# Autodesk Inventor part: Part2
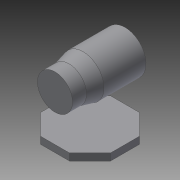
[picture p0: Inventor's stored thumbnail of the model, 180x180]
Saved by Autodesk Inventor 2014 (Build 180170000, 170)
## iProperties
Created: 2021-01
Part Number: Part2
Material: Generic
Document SubType Name: Modeling
Designer: kh
Density: 1 g/cm^3
Appearance: Default
Author: kh
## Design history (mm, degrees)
sketch "Sketch1" dims "d0" = 100
  geometry: L1 (20.711, 50)-(50, 20.711); L2 (50, 20.711)-(50, -20.711); L3 (50, -20.711)-(20.711, -50); L4 (20.711, -50)-(-20.711, -50); L5 (-20.711, -50)-(-50, -20.711); L6 (-50, -20.711)-(-50, 20.711); L7 (-50, 20.711)-(-20.711, 50); L8 (-20.711, 50)-(20.711, 50); L9 (0, 0)-(0, 50); 4 further points
  constraints: 18 end point, 3 coincident, 1 midpoint, 1 vertical, 20 other
  dimensions: "d12" = 50 distance of L9.start L9.end
extrude "Extrusion1" new body sketch "Sketch1" distance "d1" = 10; taper "d2" = 0 deg
workplane "Work Plane1"
sketch "Sketch2"
  geometry: L1 (-19.134, 0)-(19.134, 0) reference; L2 (-19.134, 0)-(-19.134, 10) reference; L3 (19.134, 10)-(-19.134, 10) reference; L4 (19.134, 0)-(19.134, 10) reference; L5 (-46.194, 0)-(-19.134, 0) reference; L6 (-46.194, 0)-(-46.194, 10) reference; L7 (-19.134, 10)-(-46.194, 10) reference; L8 (-19.134, 0)-(-19.134, 10) reference; L9 (19.134, 0)-(46.194, 0) reference; L10 (19.134, 0)-(19.134, 10) reference; L11 (46.194, 10)-(19.134, 10) reference; L12 (46.194, 0)-(46.194, 10) reference; L13 (-50, 75)-(-30, 75); L14 (-30, 75)-(-30, 100); L15 (-30, 100)-(-50, 100); L16 (-50, 100)-(-50, 75); L17 (-30, 75)-(-10, 75); L18 (-10, 75)-(-10, 105); L19 (-30, 100)-(-30, 75); L20 (-10, 75)-(50, 75); L21 (50, 75)-(50, 105); L22 (50, 105)-(-10, 105); L23 (-10, 105)-(-10, 75); L24 (-30, 100)-(-10, 105); L25 (-50, 0)-(-20.711, 0) reference; L26 (-50, 0)-(-50, 10) reference; L27 (-20.711, 10)-(-50, 10) reference; L28 (-20.711, 0)-(-20.711, 10) reference; L29 (-20.711, 0)-(20.711, 0) reference; L30 (-20.711, 0)-(-20.711, 10) reference; L31 (20.711, 10)-(-20.711, 10) reference; L32 (20.711, 0)-(20.711, 10) reference; L33 (20.711, 0)-(50, 0) reference; L34 (20.711, 0)-(20.711, 10) reference; L35 (50, 10)-(20.711, 10) reference; L36 (50, 0)-(50, 10) reference
  constraints: 24 end point, 5 parallel, 3 horizontal, 3 perpendicular, 1 collinear
  dimensions: "d5" = 50 diameter of L15 L13; "d7" = 60 diameter of L22 L20; "d8" = 100 distance between parallel lines of L21 L16; "d9" = 40 distance between parallel lines of L16 L18; "d10" = 20 distance between parallel lines of L16 L14; "d14" = 75 distance of L13.start L25.start
revolve "Revolution2" sketch "Sketch2" stored, may be unused: angle "d15" = 90 deg
workplane "Work Plane2"
sketch "Sketch3"
  geometry: L1 (-50, 50)-(-50, 100) reference; L2 (50, 45)-(50, 105) reference; L3 (-50, 75)-(50, 75); L4 (50, 75)-(35, 75); L5 (35, 75)-(35, 96); L6 (35, 96)-(50, 96); L7 (50, 96)-(50, 75); L8 (35, 75)-(-7, 75); L9 (-7, 75)-(-7, 99); L10 (-7, 99)-(35, 99); L11 (35, 99)-(35, 75); L12 (-7, 75)-(-19, 75); L13 (-19, 75)-(-19, 96); L14 (-19, 96)-(-7, 96); L15 (-7, 96)-(-7, 75); L16 (-19, 75)-(-37, 75); L17 (-37, 75)-(-37, 92.5); L18 (-37, 92.5)-(-19, 92.5); L19 (-19, 92.5)-(-19, 75); L20 (-37, 75)-(-41, 75); L21 (-41, 75)-(-41, 91); L22 (-41, 91)-(-37, 91); L23 (-37, 91)-(-37, 75); L24 (-41, 75)-(-44, 75); L25 (-44, 75)-(-44, 85.5); L26 (-44, 85.5)-(-41, 85.5); L27 (-41, 85.5)-(-41, 75); 1 further point
  constraints: 50 end point, 12 parallel, 6 horizontal, 6 perpendicular, 2 midpoint
  dimensions: "d17" = 15 distance between parallel lines of L5 L7; "d18" = 42 distance between parallel lines of L15 L5; "d19" = 12 distance between parallel lines of L13 L15; "d20" = 18 distance between parallel lines of L17 L13; "d21" = 4 distance between parallel lines of L17 L21; "d22" = 3 distance between parallel lines of L21 L25; "d23" = 42 diameter of L6 L3; "d24" = 48 diameter of L10 L3; "d25" = 42 diameter of L14 L12; "d26" = 35 diameter of L18 L16; "d27" = 32 diameter of L22 L3; "d28" = 21 diameter of L26 L24
revolve "Revolution3" sketch "Sketch3" stored, may be unused: angle "d29" = 90 deg
fillet "Fillet1" dims "d30" = 0.3
fillet "Fillet2" dims "d31" = 3
fillet "Fillet3" dims "d32" = 3
chamfer "Chamfer1" distance "d33" = 1; stored, may be unused: second distance "d34" = 2, angle "d35" = 45 deg
body "Solid1"
node "Projected Loop1"
node "Projected Loop2"
node "Projected Loop3"
node "Projected Loop4"
node "Projected Loop5"
node "Projected Loop6"
other parameters: "d3" = 0, "d16" = 0
